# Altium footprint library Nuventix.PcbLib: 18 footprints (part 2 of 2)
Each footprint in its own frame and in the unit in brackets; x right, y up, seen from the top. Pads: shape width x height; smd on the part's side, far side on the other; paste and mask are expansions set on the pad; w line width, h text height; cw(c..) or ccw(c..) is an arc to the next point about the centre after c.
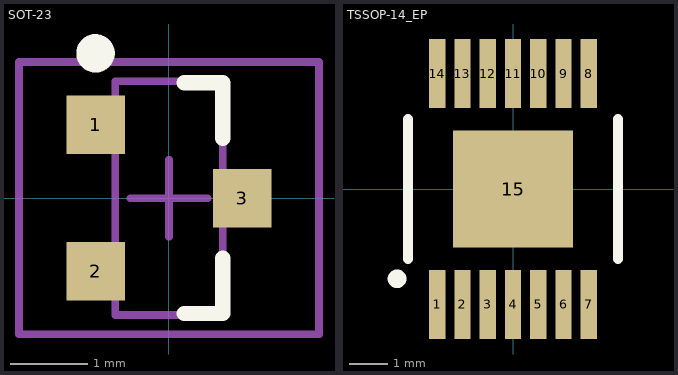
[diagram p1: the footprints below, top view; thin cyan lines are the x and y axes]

## SOT-23 [mm] "SOT23, 3-Leads, Body 3.0x2.6mm (max), Pitch 0.95mm, IPC Medium Density, from National MF03A"
height 1.12
pads (3):
  rect 0.76x0.76 smd: 1(-0.955,0.953) 2(-0.955,-0.953) 3(0.955,0)
Top Overlay:
  circle w0.25: c-0.955,1.883 r0.125
  lines w0.2: 0.2,-1.5 0.7,-1.5 0.7,-0.78 ; 0.2,1.5 0.7,1.5 0.7,0.78
Mechanical 13:
  lines w0.1: -0.7,-1.52 -0.7,1.52 0.7,1.52 0.7,-1.52 -0.7,-1.52
Mechanical 15:
  lines w0.1: -0.5,0 0.5,0 ; 0,-0.5 0,0.5 ; -1.95,-1.77 -1.95,1.77 1.95,1.77 1.95,-1.77 -1.95,-1.77
3D body: height 1.12, standoff 0.05, extent -0.7,-1.52 0.7,1.52

## TSSOP-14_EP [mm]
pads (15):
  rect 0.42x1.78 smd: 1(-1.95,-2.97) 2(-1.3,-2.97) 3(-0.65,-2.97) 4(0,-2.97) 5(0.65,-2.97) 6(1.3,-2.97) 7(1.95,-2.97) 8(1.95,2.97) 9(1.3,2.97) 10(0.65,2.97) 11(0,2.97) 12(-0.65,2.97) 13(-1.3,2.97) 14(-1.95,2.97)
  rect 3.1x3 smd: 15(0,0)
Top Overlay:
  circle w0.254: c-2.984,-2.311 r0.114
  lines w0.254: -2.7,-1.803 -2.7,1.803 ; 2.7,-1.803 2.7,1.803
